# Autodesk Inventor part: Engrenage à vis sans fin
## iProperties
Created: 2011-10
Part Number: Engrenage à vis sans fin
Material: Steel, Mild
Document SubType Name: Modeling
Designer: Laur
Density: 7.86 g/cm^3
CustomPartVersion: 1
Author: Laur
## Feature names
1. Corps de base [Revolution]
2. Dent [Revolution]
3. Motif de la dent [Circular Pattern]
